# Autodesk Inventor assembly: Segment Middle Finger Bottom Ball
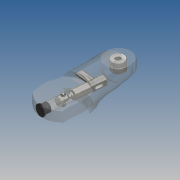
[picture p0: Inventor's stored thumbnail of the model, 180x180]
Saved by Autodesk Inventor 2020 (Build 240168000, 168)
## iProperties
Created: 2019-10
Part Number: Segment Middle Finger Bottom Ball
Document SubType Name: Assembly
Designer: yello
Author: yello
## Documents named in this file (8)
- C:\Users\yello\Documents\Mechanical Hand\Prototype 2 (Realistic Hand)\Segment Middle Finger Bottom Ball.iam
- C:\Users\yello\Documents\Mechanical Hand\Prototype 2 (Realistic Hand)\Segment Middle Finger Bottom.ipt
- C:\Users\yello\Documents\Mechanical Hand\Prototype 2 (Realistic Hand)\Push Part.ipt
- C:\Users\yello\Documents\Mechanical Hand\Prototype 2 (Realistic Hand)\Lock.ipt
- C:\Users\yello\Documents\Mechanical Hand\Prototype 2 (Realistic Hand)\Spring.ipt
- C:\Users\yello\Documents\Mechanical Hand\Prototype 2 (Realistic Hand)\Plug 4.ipt
- C:\Users\yello\Documents\Mechanical Hand\Prototype 2 (Realistic Hand)\Ball.ipt
- C:\Users\yello\Documents\Mechanical Hand\Prototype 2 (Realistic Hand)\Bearings.iam
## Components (8 placed, 7 different names)
1. Segment Middle Finger Bottom:1 — Mate:3, Mate:4, Mate:5, Mate:6, Mate:7, Mate:8, Mate:9, Mate:10, Flush:1
2. Push Part:1 — Mate:1, Mate:2, Mate:3
3. Lock:1 — Mate:1, Mate:2, Mate:4
4. Spring:1 — Mate:5
5. Plug 4:1 — Mate:6, Mate:7
6. Ball:1 — Mate:8
7. Ball:2 — Mate:9
8. Bearings:1 [sub-assembly] — Mate:10, Flush:1
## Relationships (11: Mate 10, Flush 1)
- Mate:1: Push Part:1 ↔ Lock:1
- Mate:2: Push Part:1 ↔ Lock:1
- Mate:3: Segment Middle Finger Bottom:1 ↔ Push Part:1
- Mate:4: Segment Middle Finger Bottom:1 ↔ Lock:1
- Mate:5: Segment Middle Finger Bottom:1 ↔ Spring:1
- Mate:6: Segment Middle Finger Bottom:1 ↔ Plug 4:1
- Mate:7: Segment Middle Finger Bottom:1 ↔ Plug 4:1
- Mate:8: Segment Middle Finger Bottom:1 ↔ Ball:1
- Mate:9: Segment Middle Finger Bottom:1 ↔ Ball:2
- Mate:10: Segment Middle Finger Bottom:1 ↔ Bearings:1
- Flush:1: Segment Middle Finger Bottom:1 ↔ Bearings:1
